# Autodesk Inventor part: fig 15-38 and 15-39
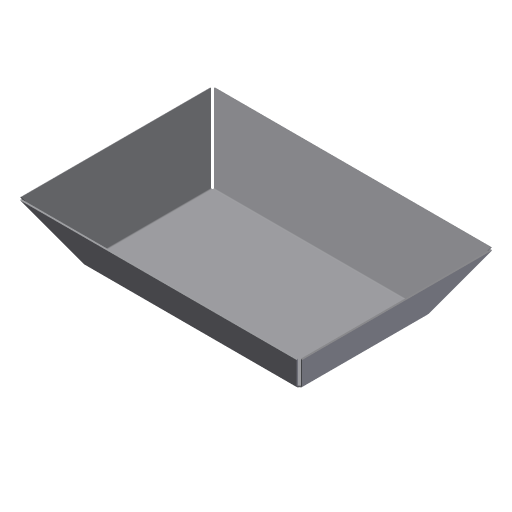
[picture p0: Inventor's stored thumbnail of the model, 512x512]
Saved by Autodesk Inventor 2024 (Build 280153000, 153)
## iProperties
Created: 2007-05
Part Number: fig 15-38 and 15-39
Document SubType Name: Sheet Metal
Designer: Administrator
Density: 1 g/cm^3
Sheet Metal Rule: Default
Material: Generic
Appearance: Default
Author: Administrator
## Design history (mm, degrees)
node "Face1"
  sketch "Sketch1"
    geometry: L1 (-17.365, -15.579)-(32.635, -15.579); L2 (32.635, -15.579)-(32.635, 14.421); L3 (32.635, 14.421)-(-17.365, 14.421); L4 (-17.365, 14.421)-(-17.365, -15.579)
    constraints: 8 end point, 2 parallel, 1 horizontal, 1 perpendicular
    dimensions: "d0" = 30 distance of L3.end L1.start; "d1" = 50 distance of L1.start L1.end
node "Flange1"
body "Solid1"
face "Plate1" dims "d13" = 0.3 (= Thickness)
sketch "Sketch2"
  geometry: L1 through (-15, 0) direction (1, 0); L2 through (0, 7.5) direction (3.7e-17, 1); L3 (0, 15)-(-30, 15); L4 (-30, 15)-(-30, 0)
  constraints: 6 end point, 1 horizontal, 1 perpendicular, 1 vertical
face "Plate2" dims "d3" = 0.3 (= BendReliefWidth), "d4" = 0.15 (= BendReliefDepth), "d5" = 0.6 (= MinimumRemnant), "d6" = 0.3 (= BendRadius), "d7" = 15, "d8" = 60 deg, "d9" = 0.3 (= BendRadius), "d10" = 1.2 (= CornerReliefSize), "d11" = 0.5, "d12" = 0.3 (= JacobiRadiusSize), "d13" = 0.3 (= Thickness), "SeamGap" = 0.01
bend "Bend1" dims "d3" = 0.3 (= BendReliefWidth), "d4" = 0.15 (= BendReliefDepth), "d5" = 0.6 (= MinimumRemnant), "d6" = 0.3 (= BendRadius), "d7" = 15, "d8" = 60 deg, "d9" = 0.3 (= BendRadius), "d13" = 0.3 (= Thickness), "SeamGap" = 0.01
feature "Corner1" dims "d7" = 15, "d8" = 60 deg, "d10" = 1.2 (= CornerReliefSize), "d11" = 0.5, "d12" = 0.3 (= JacobiRadiusSize)
other parameters: "Thickness" = 0.3, "BendRadius" = 0.3 (= Thickness), "BendReliefWidth" = 0.3 (= Thickness), "BendReliefDepth" = 0.15 (= 0.5 x Thickness), "CornerReliefSize" = 1.2 (= 4 x Thickness), "MinimumRemnant" = 0.6 (= 2 x Thickness), "TransitionRadius" = 0.3 (= BendRadius), "JacobiRadiusSize" = 0.3 (= Thickness), "d2" = 0.3 (= BendRadius), "GapSize" = 0.3 (= Thickness)
